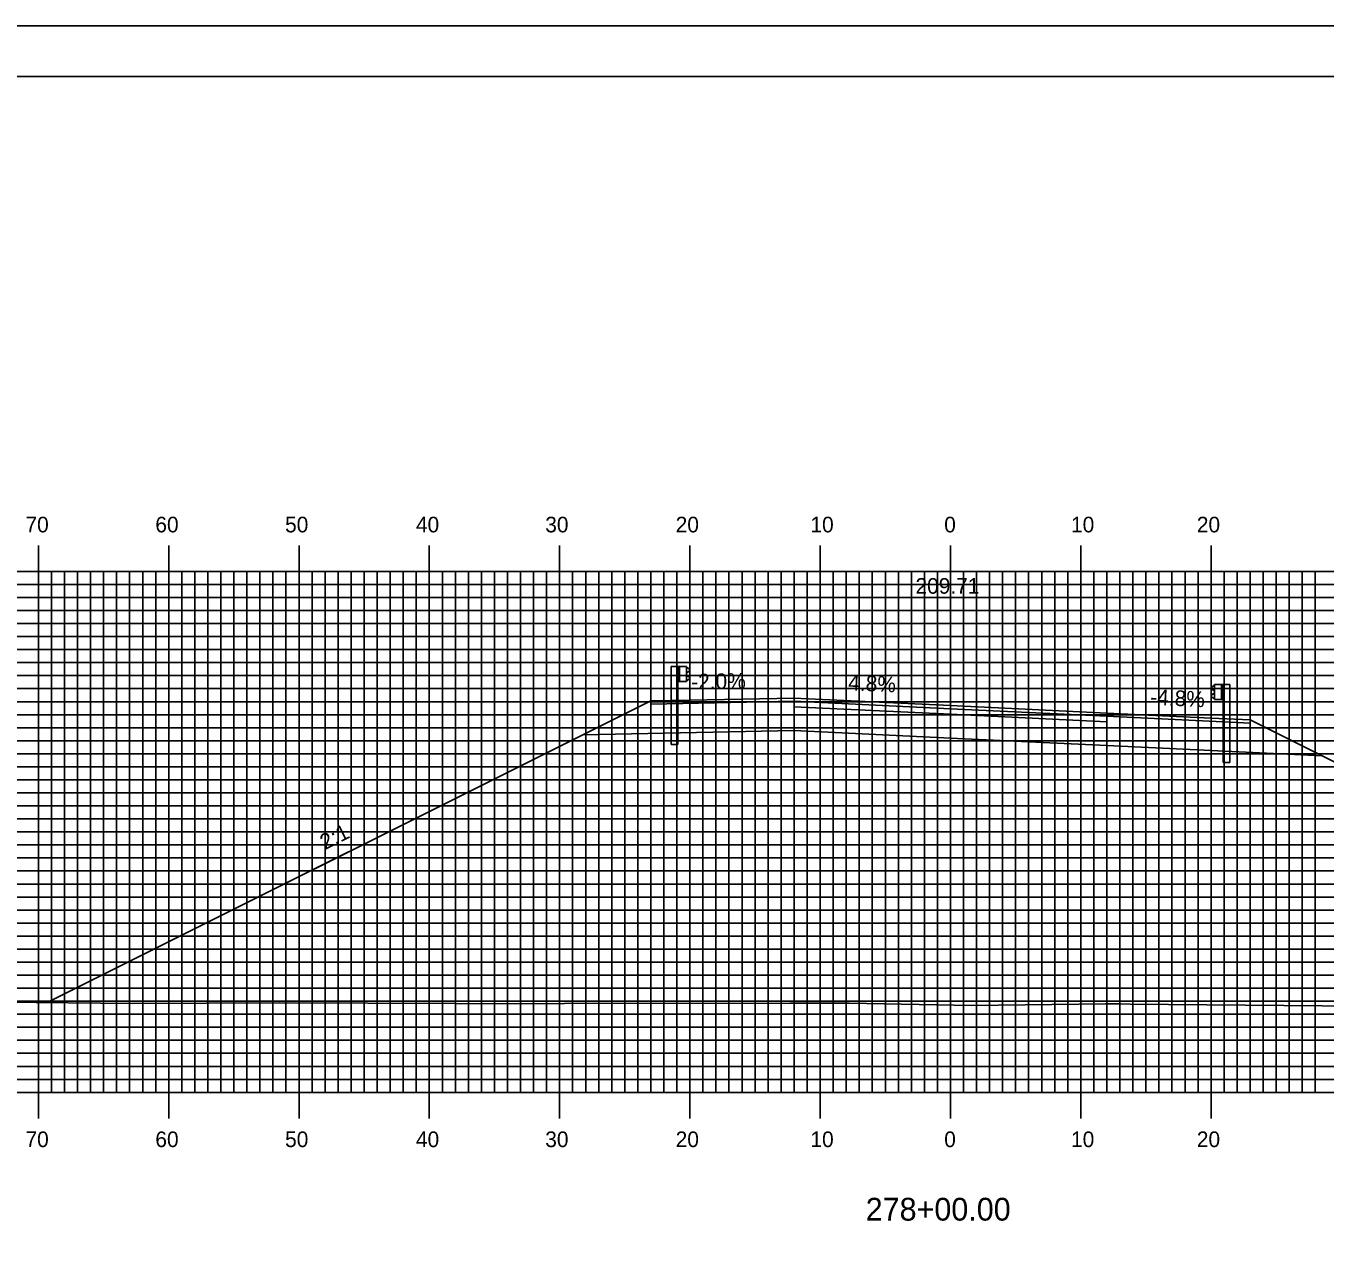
# Model space of a CAD drawing. Extents: x 1810193 to 1810536, y 442591 to 442811.
# Drawn here: x 1810287.9 to 1810387.6, y 442716.9 to 442810.5 of the extents above; entities that cross this region are included whole.
import ezdxf

# ---------------------------------------------------------------- set-up
doc = ezdxf.new("R2010")
doc.units = 0
for name, color, linetype in [('ANNOTATION', 7, 'Continuous'), ('BORDER', 7, 'Continuous'), ('D_Guardrail_Beam_Lt', 7, 'Continuous'), ('D_Guardrail_Beam_Rt', 7, 'Continuous'), ('D_Roadway_Centerline', 7, 'Continuous'), ('D_Roadway_Centerline_Text', 7, 'Continuous'), ('D_Roadway_Edge_Shoulder', 7, 'Continuous'), ('D_Roadway_Edge_TW', 7, 'Continuous'), ('D_Roadway_Pavement', 7, 'Continuous'), ('D_Roadway_SlopeLines', 7, 'Continuous'), ('D_Roadway_SubGrade', 7, 'Continuous'), ('H_V ANNOTATION', 7, 'Continuous'), ('MAJOR', 7, 'Continuous'), ('MINOR', 7, 'Continuous'), ('PLOT BOUNDARY', 7, 'Continuous'), ('S_Roadway_Centerline', 7, 'Continuous')]:
    doc.layers.add(name, color=color, linetype=linetype)

msp = doc.modelspace()

# ---------------------------------------------------------------- linework, layer by layer
at = {"layer": 'BORDER'}
msp.add_lwpolyline([(1810209.263, 442596.665), (1810529.263, 442596.665), (1810529.263, 442806.665), (1810209.263, 442806.665)], close=True, dxfattribs=at)
at = {"layer": 'D_Guardrail_Beam_Lt'}
for p, q in [((1810337.434, 442761.37), (1810337.434, 442755.37)), ((1810337.905, 442761.37), (1810337.434, 442761.37)), ((1810338.593, 442761.37), (1810337.905, 442761.37)), ((1810337.905, 442761.37), (1810337.905, 442760.203)), ((1810337.968, 442761.37), (1810337.968, 442760.203)), ((1810338.072, 442761.37), (1810338.072, 442760.203)), ((1810338.593, 442760.203), (1810338.593, 442761.37)), ((1810338.593, 442761.286), (1810338.667, 442761.272)), ((1810338.597, 442760.821), (1810338.597, 442760.751)), ((1810338.826, 442761.022), (1810338.631, 442760.886)), ((1810338.631, 442760.687), (1810338.826, 442760.551)), ((1810338.683, 442761.265), (1810338.826, 442761.165)), ((1810337.905, 442760.203), (1810338.593, 442760.203)), ((1810337.926, 442755.37), (1810337.926, 442760.203)), ((1810338.667, 442760.301), (1810338.593, 442760.286)), ((1810338.826, 442760.407), (1810338.683, 442760.307)), ((1810337.926, 442755.37), (1810337.434, 442755.37))]:
    msp.add_line(p, q, dxfattribs=at)
for centre, major_axis, start_param, end_param in [((1810338.676, 442760.821), (-0.0789, 0), 5.323254, 6.283185), ((1810338.676, 442760.751), (-0.0789, 0), 6.283185, 7.243116), ((1810338.659, 442761.231), (0.0417, 0), 0.959931, 1.376053), ((1810338.776, 442761.093), (0.0877, 0), 5.323254, 7.243116), ((1810338.776, 442760.479), (0.0877, 0), 5.323254, 7.243116), ((1810338.659, 442760.341), (0.0417, 0), 4.907132, 5.323254)]:
    msp.add_ellipse(centre, major_axis=major_axis, ratio=0.995501, start_param=start_param, end_param=end_param, dxfattribs=at)
at = {"layer": 'D_Guardrail_Beam_Rt'}
for p, q in [((1810379.044, 442759.889), (1810378.901, 442759.789)), ((1810378.901, 442759.646), (1810379.096, 442759.51)), ((1810379.134, 442759.91), (1810379.06, 442759.896)), ((1810379.134, 442759.994), (1810379.822, 442759.994)), ((1810379.134, 442758.827), (1810379.134, 442759.994)), ((1810379.655, 442759.994), (1810379.655, 442758.827)), ((1810379.759, 442759.994), (1810379.759, 442758.827)), ((1810379.822, 442759.994), (1810380.293, 442759.994)), ((1810379.822, 442759.994), (1810379.822, 442758.827)), ((1810380.293, 442759.994), (1810380.293, 442753.994)), ((1810379.096, 442759.311), (1810378.901, 442759.175)), ((1810378.901, 442759.031), (1810379.044, 442758.931)), ((1810379.06, 442758.925), (1810379.134, 442758.91)), ((1810379.13, 442759.445), (1810379.13, 442759.375)), ((1810379.822, 442758.827), (1810379.134, 442758.827)), ((1810379.801, 442753.994), (1810379.801, 442758.827)), ((1810379.801, 442753.994), (1810380.293, 442753.994))]:
    msp.add_line(p, q, dxfattribs=at)
for centre, major_axis, start_param, end_param in [((1810378.951, 442759.717), (-0.0877, 0), 5.323254, 7.243116), ((1810379.068, 442759.855), (-0.0417, 0), 4.907132, 5.323254), ((1810378.951, 442759.103), (-0.0877, 0), 5.323254, 7.243116), ((1810379.068, 442758.965), (-0.0417, 0), 0.959931, 1.376053), ((1810379.051, 442759.445), (0.0789, 0), 0, 0.959931), ((1810379.051, 442759.375), (0.0789, 0), 5.323254, 6.283185)]:
    msp.add_ellipse(centre, major_axis=major_axis, ratio=0.995501, start_param=start_param, end_param=end_param, dxfattribs=at)
at = {"layer": 'D_Roadway_Centerline'}
msp.add_lwpolyline([(1810289.545, 442735.567), (1810330.655, 442756.122), (1810335.863, 442758.726), (1810338.863, 442758.786), (1810346.863, 442758.946), (1810358.863, 442758.37), (1810370.863, 442757.794), (1810378.863, 442757.41), (1810381.863, 442757.266), (1810387.395, 442754.501), (1810426.611, 442734.892)], dxfattribs=at)
at = {"layer": 'D_Roadway_Edge_Shoulder'}
for points in [[(1810346.863, 442758.946), (1810338.863, 442758.786), (1810338.863, 442758.786), (1810335.863, 442758.726), (1810335.863, 442758.476), (1810346.863, 442758.696)], [(1810370.863, 442757.794), (1810378.863, 442757.41), (1810378.863, 442757.41), (1810381.863, 442757.266), (1810381.863, 442757.016), (1810370.863, 442757.544)]]:
    msp.add_lwpolyline(points, close=True, dxfattribs=at)
at = {"layer": 'D_Roadway_Edge_TW'}
msp.add_lwpolyline([(1810346.863, 442758.696), (1810346.863, 442758.946), (1810358.863, 442758.37), (1810370.863, 442757.794), (1810370.863, 442757.544), (1810358.863, 442758.12)], close=True, dxfattribs=at)
at = {"layer": 'D_Roadway_Pavement'}
msp.add_lwpolyline([(1810346.863, 442758.28), (1810346.863, 442758.696), (1810358.863, 442758.12), (1810370.863, 442757.544), (1810370.863, 442757.128), (1810358.863, 442757.704)], close=True, dxfattribs=at)
for points in [[(1810346.863, 442758.696), (1810346.863, 442758.28)], [(1810370.863, 442757.544), (1810370.863, 442757.128)]]:
    msp.add_lwpolyline(points, dxfattribs=at)
at = {"layer": 'D_Roadway_SlopeLines'}
for points in [[(1810335.863, 442758.726), (1810289.545, 442735.567)], [(1810381.863, 442757.266), (1810426.611, 442734.892)]]:
    msp.add_lwpolyline(points, dxfattribs=at)
at = {"layer": 'D_Roadway_SubGrade'}
for points in [[(1810346.863, 442758.28), (1810346.863, 442758.696), (1810335.863, 442758.476), (1810335.863, 442758.726), (1810330.655, 442756.122), (1810346.863, 442756.446)], [(1810346.863, 442756.446), (1810346.863, 442758.696), (1810346.863, 442758.28), (1810358.863, 442757.704), (1810370.863, 442757.128), (1810370.863, 442757.544), (1810370.863, 442755.294), (1810358.863, 442755.87)], [(1810370.863, 442757.128), (1810370.863, 442757.544), (1810381.863, 442757.016), (1810381.863, 442757.266), (1810387.395, 442754.501), (1810370.863, 442755.294)]]:
    msp.add_lwpolyline(points, close=True, dxfattribs=at)
at = {"layer": 'MAJOR'}
for p, q in [((1810288.863, 442770.669), (1810288.863, 442768.665)), ((1810298.863, 442770.669), (1810298.863, 442768.665)), ((1810308.863, 442770.669), (1810308.863, 442768.665)), ((1810318.863, 442770.669), (1810318.863, 442768.665)), ((1810328.863, 442770.669), (1810328.863, 442768.665)), ((1810338.863, 442770.669), (1810338.863, 442768.665)), ((1810348.863, 442770.669), (1810348.863, 442768.665)), ((1810358.863, 442770.669), (1810358.863, 442768.665)), ((1810368.863, 442770.669), (1810368.863, 442768.665)), ((1810378.863, 442770.669), (1810378.863, 442768.665)), ((1810218.863, 442768.665), (1810498.863, 442768.665)), ((1810218.863, 442768.665), (1810498.863, 442768.665)), ((1810288.863, 442728.665), (1810288.863, 442768.665)), ((1810298.863, 442728.665), (1810298.863, 442768.665)), ((1810308.863, 442728.665), (1810308.863, 442768.665)), ((1810318.863, 442728.665), (1810318.863, 442768.665)), ((1810328.863, 442728.665), (1810328.863, 442768.665)), ((1810338.863, 442728.665), (1810338.863, 442768.665)), ((1810348.863, 442728.665), (1810348.863, 442768.665)), ((1810358.863, 442728.665), (1810358.863, 442768.665)), ((1810368.863, 442728.665), (1810368.863, 442768.665)), ((1810378.863, 442728.665), (1810378.863, 442768.665)), ((1810218.863, 442763.665), (1810498.863, 442763.665)), ((1810218.863, 442758.665), (1810498.863, 442758.665)), ((1810218.863, 442753.665), (1810498.863, 442753.665)), ((1810218.863, 442748.665), (1810498.863, 442748.665)), ((1810218.863, 442743.665), (1810498.863, 442743.665)), ((1810218.863, 442738.665), (1810498.863, 442738.665)), ((1810218.863, 442733.665), (1810498.863, 442733.665)), ((1810218.863, 442728.665), (1810498.863, 442728.665)), ((1810218.863, 442728.665), (1810498.863, 442728.665)), ((1810288.863, 442726.661), (1810288.863, 442728.665)), ((1810298.863, 442726.661), (1810298.863, 442728.665)), ((1810308.863, 442726.661), (1810308.863, 442728.665)), ((1810318.863, 442726.661), (1810318.863, 442728.665)), ((1810328.863, 442726.661), (1810328.863, 442728.665)), ((1810338.863, 442726.661), (1810338.863, 442728.665)), ((1810348.863, 442726.661), (1810348.863, 442728.665)), ((1810358.863, 442726.661), (1810358.863, 442728.665)), ((1810368.863, 442726.661), (1810368.863, 442728.665)), ((1810378.863, 442726.661), (1810378.863, 442728.665))]:
    msp.add_line(p, q, dxfattribs=at)
at = {"layer": 'MINOR'}
for p, q in [((1810289.863, 442728.665), (1810289.863, 442768.665)), ((1810290.863, 442728.665), (1810290.863, 442768.665)), ((1810291.863, 442728.665), (1810291.863, 442768.665)), ((1810292.863, 442728.665), (1810292.863, 442768.665)), ((1810293.863, 442728.665), (1810293.863, 442768.665)), ((1810294.863, 442728.665), (1810294.863, 442768.665)), ((1810295.863, 442728.665), (1810295.863, 442768.665)), ((1810296.863, 442728.665), (1810296.863, 442768.665)), ((1810297.863, 442728.665), (1810297.863, 442768.665)), ((1810299.863, 442728.665), (1810299.863, 442768.665)), ((1810300.863, 442728.665), (1810300.863, 442768.665)), ((1810301.863, 442728.665), (1810301.863, 442768.665)), ((1810302.863, 442728.665), (1810302.863, 442768.665)), ((1810303.863, 442728.665), (1810303.863, 442768.665)), ((1810304.863, 442728.665), (1810304.863, 442768.665)), ((1810305.863, 442728.665), (1810305.863, 442768.665)), ((1810306.863, 442728.665), (1810306.863, 442768.665)), ((1810307.863, 442728.665), (1810307.863, 442768.665)), ((1810309.863, 442728.665), (1810309.863, 442768.665)), ((1810310.863, 442728.665), (1810310.863, 442768.665)), ((1810311.863, 442728.665), (1810311.863, 442768.665)), ((1810312.863, 442728.665), (1810312.863, 442768.665)), ((1810313.863, 442728.665), (1810313.863, 442768.665)), ((1810314.863, 442728.665), (1810314.863, 442768.665)), ((1810315.863, 442728.665), (1810315.863, 442768.665)), ((1810316.863, 442728.665), (1810316.863, 442768.665)), ((1810317.863, 442728.665), (1810317.863, 442768.665)), ((1810319.863, 442728.665), (1810319.863, 442768.665)), ((1810320.863, 442728.665), (1810320.863, 442768.665)), ((1810321.863, 442728.665), (1810321.863, 442768.665)), ((1810322.863, 442728.665), (1810322.863, 442768.665)), ((1810323.863, 442728.665), (1810323.863, 442768.665)), ((1810324.863, 442728.665), (1810324.863, 442768.665)), ((1810325.863, 442728.665), (1810325.863, 442768.665)), ((1810326.863, 442728.665), (1810326.863, 442768.665)), ((1810327.863, 442728.665), (1810327.863, 442768.665)), ((1810329.863, 442728.665), (1810329.863, 442768.665)), ((1810330.863, 442728.665), (1810330.863, 442768.665)), ((1810331.863, 442728.665), (1810331.863, 442768.665)), ((1810332.863, 442728.665), (1810332.863, 442768.665)), ((1810333.863, 442728.665), (1810333.863, 442768.665)), ((1810334.863, 442728.665), (1810334.863, 442768.665)), ((1810335.863, 442728.665), (1810335.863, 442768.665)), ((1810336.863, 442728.665), (1810336.863, 442768.665)), ((1810337.863, 442728.665), (1810337.863, 442768.665)), ((1810339.863, 442728.665), (1810339.863, 442768.665)), ((1810340.863, 442728.665), (1810340.863, 442768.665)), ((1810341.863, 442728.665), (1810341.863, 442768.665)), ((1810342.863, 442728.665), (1810342.863, 442768.665)), ((1810343.863, 442728.665), (1810343.863, 442768.665)), ((1810344.863, 442728.665), (1810344.863, 442768.665)), ((1810345.863, 442728.665), (1810345.863, 442768.665)), ((1810346.863, 442728.665), (1810346.863, 442768.665)), ((1810347.863, 442728.665), (1810347.863, 442768.665)), ((1810349.863, 442728.665), (1810349.863, 442768.665)), ((1810350.863, 442728.665), (1810350.863, 442768.665)), ((1810351.863, 442728.665), (1810351.863, 442768.665)), ((1810352.863, 442728.665), (1810352.863, 442768.665)), ((1810353.863, 442728.665), (1810353.863, 442768.665)), ((1810354.863, 442728.665), (1810354.863, 442768.665)), ((1810355.863, 442728.665), (1810355.863, 442768.665)), ((1810356.863, 442728.665), (1810356.863, 442768.665)), ((1810357.863, 442728.665), (1810357.863, 442768.665)), ((1810359.863, 442728.665), (1810359.863, 442768.665)), ((1810360.863, 442728.665), (1810360.863, 442768.665)), ((1810361.863, 442728.665), (1810361.863, 442768.665)), ((1810362.863, 442728.665), (1810362.863, 442768.665)), ((1810363.863, 442728.665), (1810363.863, 442768.665)), ((1810364.863, 442728.665), (1810364.863, 442768.665)), ((1810365.863, 442728.665), (1810365.863, 442768.665)), ((1810366.863, 442728.665), (1810366.863, 442768.665)), ((1810367.863, 442728.665), (1810367.863, 442768.665)), ((1810369.863, 442728.665), (1810369.863, 442768.665)), ((1810370.863, 442728.665), (1810370.863, 442768.665)), ((1810371.863, 442728.665), (1810371.863, 442768.665)), ((1810372.863, 442728.665), (1810372.863, 442768.665)), ((1810373.863, 442728.665), (1810373.863, 442768.665)), ((1810374.863, 442728.665), (1810374.863, 442768.665)), ((1810375.863, 442728.665), (1810375.863, 442768.665)), ((1810376.863, 442728.665), (1810376.863, 442768.665)), ((1810377.863, 442728.665), (1810377.863, 442768.665)), ((1810379.863, 442728.665), (1810379.863, 442768.665)), ((1810380.863, 442728.665), (1810380.863, 442768.665)), ((1810381.863, 442728.665), (1810381.863, 442768.665)), ((1810382.863, 442728.665), (1810382.863, 442768.665)), ((1810383.863, 442728.665), (1810383.863, 442768.665)), ((1810384.863, 442728.665), (1810384.863, 442768.665)), ((1810385.863, 442728.665), (1810385.863, 442768.665)), ((1810386.863, 442728.665), (1810386.863, 442768.665)), ((1810218.863, 442767.665), (1810498.863, 442767.665)), ((1810218.863, 442766.665), (1810498.863, 442766.665)), ((1810218.863, 442765.665), (1810498.863, 442765.665)), ((1810218.863, 442764.665), (1810498.863, 442764.665)), ((1810218.863, 442762.665), (1810498.863, 442762.665)), ((1810218.863, 442761.665), (1810498.863, 442761.665)), ((1810218.863, 442760.665), (1810498.863, 442760.665)), ((1810218.863, 442759.665), (1810498.863, 442759.665)), ((1810218.863, 442757.665), (1810498.863, 442757.665)), ((1810218.863, 442756.665), (1810498.863, 442756.665)), ((1810218.863, 442755.665), (1810498.863, 442755.665)), ((1810218.863, 442754.665), (1810498.863, 442754.665)), ((1810218.863, 442752.665), (1810498.863, 442752.665)), ((1810218.863, 442751.665), (1810498.863, 442751.665)), ((1810218.863, 442750.665), (1810498.863, 442750.665)), ((1810218.863, 442749.665), (1810498.863, 442749.665)), ((1810218.863, 442747.665), (1810498.863, 442747.665)), ((1810218.863, 442746.665), (1810498.863, 442746.665)), ((1810218.863, 442745.665), (1810498.863, 442745.665)), ((1810218.863, 442744.665), (1810498.863, 442744.665)), ((1810218.863, 442742.665), (1810498.863, 442742.665)), ((1810218.863, 442741.665), (1810498.863, 442741.665)), ((1810218.863, 442740.665), (1810498.863, 442740.665)), ((1810218.863, 442739.665), (1810498.863, 442739.665)), ((1810218.863, 442737.665), (1810498.863, 442737.665)), ((1810218.863, 442736.665), (1810498.863, 442736.665)), ((1810218.863, 442735.665), (1810498.863, 442735.665)), ((1810218.863, 442734.665), (1810498.863, 442734.665)), ((1810218.863, 442732.665), (1810498.863, 442732.665)), ((1810218.863, 442731.665), (1810498.863, 442731.665)), ((1810218.863, 442730.665), (1810498.863, 442730.665)), ((1810218.863, 442729.665), (1810498.863, 442729.665))]:
    msp.add_line(p, q, dxfattribs=at)
at = {"layer": 'PLOT BOUNDARY'}
msp.add_lwpolyline([(1810193.077, 442590.547), (1810533.077, 442590.547), (1810533.077, 442810.547), (1810193.077, 442810.547)], close=True, dxfattribs=at)
at = {"layer": 'S_Roadway_Centerline'}
msp.add_lwpolyline([(1810218.863, 442735.685), (1810221.023, 442735.712), (1810221.348, 442735.716), (1810232.472, 442735.587), (1810242.845, 442735.648), (1810247.999, 442735.806), (1810264.074, 442735.938), (1810267.524, 442735.861), (1810272.56, 442735.895), (1810286.214, 442735.602), (1810296.116, 442735.497), (1810307.396, 442735.531), (1810320.875, 442735.497), (1810325.928, 442735.47), (1810329.246, 442735.478), (1810346.559, 442735.523), (1810351.088, 442735.511), (1810360.465, 442735.328), (1810370.762, 442735.46), (1810371.832, 442735.462), (1810372.661, 442735.446), (1810393.273, 442735.265)], dxfattribs=at)

# ---------------------------------------------------------------- texts
at = {"layer": 'ANNOTATION'}
for s, rotation, p in [('-2.0%', 1.14576, (1810338.97, 442759.589)), ('4.8%', 357.25191, (1810350.993, 442759.55)), ('-4.8%', 357.25191, (1810374.172, 442758.438)), ('2:1', 26.56505, (1810310.849, 442747.255))]:
    msp.add_text(s, height=1.2, rotation=rotation, dxfattribs=at).set_placement(p)
at = {"layer": 'D_Roadway_Centerline'}
for s, p in [('C', (1810358.858, 442758.37)), ('L', (1810358.863, 442758.363))]:
    msp.add_text(s, height=0.0146, dxfattribs=at).set_placement(p)
at = {"layer": 'D_Roadway_Centerline_Text'}
msp.add_text('209.71', height=1.2, dxfattribs=at).set_placement((1810356.177, 442766.954))
at = {"layer": 'H_V ANNOTATION'}
for s, height, p in [('70', 1.2, (1810287.868, 442771.665)), ('60', 1.2, (1810297.836, 442771.665)), ('50', 1.2, (1810307.793, 442771.665)), ('40', 1.2, (1810317.836, 442771.665)), ('30', 1.2, (1810327.761, 442771.665)), ('20', 1.2, (1810337.771, 442771.665)), ('10', 1.2, (1810348.114, 442771.665)), ('0', 1.2, (1810358.382, 442771.665)), ('10', 1.2, (1810368.114, 442771.665)), ('20', 1.2, (1810377.771, 442771.665)), ('70', 1.2, (1810287.868, 442724.465)), ('60', 1.2, (1810297.836, 442724.465)), ('50', 1.2, (1810307.793, 442724.465)), ('40', 1.2, (1810317.836, 442724.465)), ('30', 1.2, (1810327.761, 442724.465)), ('20', 1.2, (1810337.771, 442724.465)), ('10', 1.2, (1810348.114, 442724.465)), ('0', 1.2, (1810358.382, 442724.465)), ('10', 1.2, (1810368.114, 442724.465)), ('20', 1.2, (1810377.771, 442724.465)), ('278+00.00', 1.75, (1810352.355, 442718.821))]:
    msp.add_text(s, height=height, dxfattribs=at).set_placement(p)

doc.saveas('drawing.dxf')
